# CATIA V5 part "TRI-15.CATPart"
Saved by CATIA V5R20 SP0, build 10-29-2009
Part number: _TRI-15
Definition: NONE
Nomenclature: _TRI-15
Source: Unknown
Description: PART-_TRI-15-DESC
Bounding box of the stored display mesh (mm): x 0 to 17.5, y -7.5 to 7.5, z -7.5 to 7.5
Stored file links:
  C:\Users\Utente\Desktop\IO LAVORO\3D X SITO CF\X SITO\PLASTICA\TRI\TRI-15.CATPart
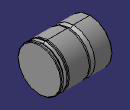
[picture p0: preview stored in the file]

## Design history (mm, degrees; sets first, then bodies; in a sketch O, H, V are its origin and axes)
Body1 "_TRI-15" (main body)
  Solid1: solid without history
